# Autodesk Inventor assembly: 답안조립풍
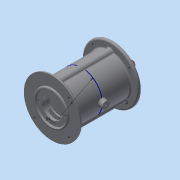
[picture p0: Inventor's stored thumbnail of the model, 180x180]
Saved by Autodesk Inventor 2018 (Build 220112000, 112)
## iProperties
Created: 2024-10
Part Number: 답안조립풍
Material: 일반
Document SubType Name: Assembly
Designer: home
Author: home
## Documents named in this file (3)
- C:\Users\home\Desktop\741004V1007\답안조립풍.iam
- C:\Users\home\Desktop\741004V1007\본체1.ipt
- C:\Users\home\Desktop\741004V1007\스러스트 볼베어링 512 02.ipt
